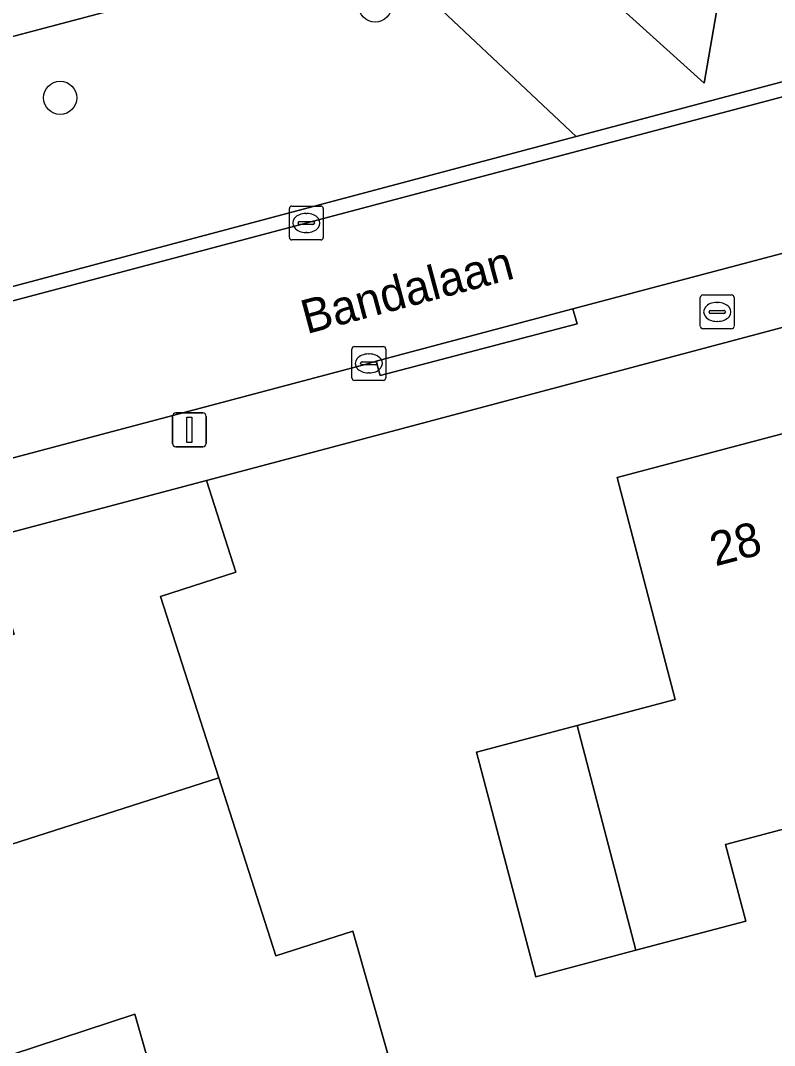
# Model space of a CAD drawing. Extents: x 162879 to 165540, y 384011 to 385181.
# Drawn here: x 163800.4 to 163822.64, y 384414.7 to 384444.93 of the extents above; entities that cross this region are included whole.
import ezdxf

# ---------------------------------------------------------------- set-up
doc = ezdxf.new("R2010")
doc.units = 0
for name, color, linetype in [('IMGEO_Boom', 7, 'Continuous'), ('IMGEO_Brandkraan', 7, 'Continuous'), ('IMGEO_Erf', 7, 'Continuous'), ('IMGEO_Groenvoorziening', 7, 'Continuous'), ('IMGEO_Haag', 7, 'Continuous'), ('IMGEO_Kolk', 7, 'Continuous'), ('IMGEO_Lichtmast', 7, 'Continuous'), ('IMGEO_Muur', 7, 'Continuous'), ('IMGEO_Openbare_ruimte_label', 7, 'Continuous'), ('IMGEO_Pand', 7, 'Continuous'), ('IMGEO_Pand_nummerreeks', 7, 'Continuous'), ('IMGEO_Rijbaan_lokaal_open', 7, 'Continuous'), ('IMGEO_Voetpad_halfverhard', 7, 'Continuous'), ('IMGEO_Voetpad_open', 7, 'Continuous')]:
    doc.layers.add(name, color=color, linetype=linetype)

msp = doc.modelspace()

# ---------------------------------------------------------------- linework, layer by layer
at = {"layer": 'IMGEO_Boom'}
for centre in [(163810.857, 384445.378), (163801.568, 384442.651)]:
    msp.add_circle(centre, 0.489, dxfattribs=at)
at = {"layer": 'IMGEO_Brandkraan'}
for p, q in [((163820.447, 384435.912), (163820.447, 384436.764)), ((163820.522, 384436.838), (163821.374, 384436.838)), ((163821.448, 384436.764), (163821.448, 384435.912)), ((163820.706, 384436.332), (163820.706, 384436.344)), ((163820.749, 384436.381), (163821.147, 384436.381)), ((163820.935, 384436.618), (163820.96, 384436.618)), ((163821.19, 384436.344), (163821.19, 384436.332)), ((163821.144, 384436.295), (163820.746, 384436.295)), ((163820.958, 384436.058), (163820.933, 384436.058)), ((163821.374, 384435.838), (163820.522, 384435.838))]:
    msp.add_line(p, q, dxfattribs=at)
for points in [[(163820.447, 384435.912), (163820.447, 384436.764)], [(163820.522, 384436.838), (163821.374, 384436.838)], [(163821.448, 384436.764), (163821.448, 384435.912)], [(163821.374, 384435.838), (163820.522, 384435.838)]]:
    msp.add_lwpolyline(points, dxfattribs=at)
for centre, radius, start, end in [((163820.524, 384436.762), 0.0765, 91.552, 178.448), ((163820.524, 384436.762), 0.0765, 91.552, 178.448), ((163821.372, 384436.762), 0.0765, 1.552, 88.448), ((163821.372, 384436.762), 0.0765, 1.552, 88.448), ((163820.746, 384436.341), 0.0403, 85.8775, 175.7526), ((163821.151, 384436.343), 0.0386, 1.7309, 96.639), ((163820.743, 384436.331), 0.0366, 178.938, 274.7102), ((163821.147, 384436.338), 0.043, 264.8664, 352.4533), ((163820.524, 384435.914), 0.0765, 181.552, 268.448), ((163820.524, 384435.914), 0.0765, 181.552, 268.448), ((163821.372, 384435.914), 0.0765, 271.552, 358.448), ((163821.372, 384435.914), 0.0765, 271.552, 358.448)]:
    msp.add_arc(centre, radius, start, end, dxfattribs=at)
for centre, major_axis, ratio, start_param, end_param in [((163820.934, 384436.338), (-0.387, 0.002), 0.722429, 4.712389, 7.853982), ((163820.959, 384436.338), (-0.39, 0.002), 0.717154, 1.570796, 4.712389)]:
    msp.add_ellipse(centre, major_axis=major_axis, ratio=ratio, start_param=start_param, end_param=end_param, dxfattribs=at)
at = {"layer": 'IMGEO_Erf'}
for points in [[(163844.085, 384441.522), (163811.331, 384432.813), (163805.887, 384431.366), (163806.752, 384428.658), (163804.524, 384427.941), (163806.243, 384422.592), (163807.931, 384417.34), (163810.195, 384418.068), (163811.223, 384414.483)], [(163826.572, 384422.049), (163821.196, 384420.622), (163821.794, 384418.37), (163818.545, 384417.508), (163815.6, 384416.726), (163813.843, 384423.347), (163816.817, 384424.136), (163819.71, 384424.904), (163817.994, 384431.451), (163823.678, 384432.96)], [(163804.622, 384412.635), (163803.766, 384415.619), (163797.929, 384413.701), (163797.388, 384415.352), (163796.816, 384415.168), (163795.534, 384419.157), (163793.736, 384424.755), (163800.21, 384426.836), (163799.316, 384429.621), (163790.794, 384427.333)]]:
    msp.add_lwpolyline(points, dxfattribs=at)
at = {"layer": 'IMGEO_Groenvoorziening'}
for points in [[(163846.564, 384455.941), (163848.959, 384450.828), (163848.448, 384449.933), (163839.54, 384447.563), (163836.128, 384446.655), (163824.084, 384443.45), (163816.786, 384441.509), (163786.859, 384433.545), (163782.654, 384432.426), (163775.562, 384430.545), (163773.371, 384437.23)], [(163773.081, 384436.833), (163775.3, 384430.061), (163777.69, 384430.711), (163782.356, 384431.947), (163812.597, 384439.959), (163829.593, 384444.462), (163830.022, 384444.577), (163841.66, 384447.709), (163843.285, 384448.142), (163848.713, 384449.59)]]:
    msp.add_lwpolyline(points, dxfattribs=at)
for points in [[(163826.162, 384451.348), (163822.181, 384450.302), (163821.789, 384450.2), (163820.561, 384443.081), (163814.756, 384448.336), (163810.694, 384447.259), (163816.786, 384441.509), (163824.084, 384443.45)], [(163821.789, 384450.2), (163814.756, 384448.336), (163820.561, 384443.081)], [(163816.786, 384441.509), (163810.694, 384447.259), (163790.298, 384441.853), (163786.859, 384433.545)]]:
    msp.add_lwpolyline(points, close=True, dxfattribs=at)
at = {"layer": 'IMGEO_Haag'}
for points in [[(163846.564, 384455.941), (163848.959, 384450.828), (163848.448, 384449.933), (163839.54, 384447.563), (163836.128, 384446.655), (163824.084, 384443.45), (163816.786, 384441.509), (163786.859, 384433.545), (163782.654, 384432.426), (163775.562, 384430.545), (163773.371, 384437.23)], [(163773.081, 384436.833), (163775.3, 384430.061), (163777.69, 384430.711), (163782.356, 384431.947), (163812.597, 384439.959), (163829.593, 384444.462), (163830.022, 384444.577), (163841.66, 384447.709), (163843.285, 384448.142), (163848.713, 384449.59)]]:
    msp.add_lwpolyline(points, dxfattribs=at)
at = {"layer": 'IMGEO_Kolk'}
for p, q in [((163808.327, 384438.535), (163808.327, 384439.387)), ((163808.402, 384439.461), (163809.254, 384439.461)), ((163809.328, 384439.387), (163809.328, 384438.535)), ((163808.815, 384439.241), (163808.84, 384439.241)), ((163808.586, 384438.955), (163808.586, 384438.967)), ((163809.024, 384438.918), (163808.626, 384438.918)), ((163808.629, 384439.004), (163809.027, 384439.004)), ((163809.07, 384438.967), (163809.07, 384438.955)), ((163809.254, 384438.461), (163808.402, 384438.461)), ((163808.838, 384438.681), (163808.813, 384438.681)), ((163810.171, 384434.391), (163810.171, 384435.243)), ((163810.246, 384435.317), (163811.098, 384435.317)), ((163811.172, 384435.243), (163811.172, 384434.391)), ((163810.473, 384434.86), (163810.871, 384434.86)), ((163810.659, 384435.097), (163810.684, 384435.097)), ((163810.43, 384434.811), (163810.43, 384434.823)), ((163810.868, 384434.774), (163810.47, 384434.774)), ((163810.682, 384434.537), (163810.657, 384434.537)), ((163810.914, 384434.823), (163810.914, 384434.811)), ((163811.098, 384434.317), (163810.246, 384434.317))]:
    msp.add_line(p, q, dxfattribs=at)
for points in [[(163808.327, 384438.535), (163808.327, 384439.387)], [(163808.402, 384439.461), (163809.254, 384439.461)], [(163809.328, 384439.387), (163809.328, 384438.535)], [(163809.254, 384438.461), (163808.402, 384438.461)], [(163810.171, 384434.391), (163810.171, 384435.243)], [(163810.246, 384435.317), (163811.098, 384435.317)], [(163811.172, 384435.243), (163811.172, 384434.391)], [(163811.098, 384434.317), (163810.246, 384434.317)]]:
    msp.add_lwpolyline(points, dxfattribs=at)
for centre, radius, start, end in [((163808.404, 384439.385), 0.0765, 91.552, 178.448), ((163808.404, 384439.385), 0.0765, 91.552, 178.448), ((163809.252, 384439.385), 0.0765, 1.552, 88.448), ((163809.252, 384439.385), 0.0765, 1.552, 88.448), ((163808.626, 384438.964), 0.0403, 85.8775, 175.7526), ((163808.623, 384438.954), 0.0366, 178.938, 274.7102), ((163809.027, 384438.961), 0.043, 264.8664, 352.4533), ((163809.031, 384438.966), 0.0386, 1.7309, 96.639), ((163808.404, 384438.537), 0.0765, 181.552, 268.448), ((163808.404, 384438.537), 0.0765, 181.552, 268.448), ((163809.252, 384438.537), 0.0765, 271.552, 358.448), ((163809.252, 384438.537), 0.0765, 271.552, 358.448), ((163810.248, 384435.241), 0.0765, 91.552, 178.448), ((163810.248, 384435.241), 0.0765, 91.552, 178.448), ((163811.096, 384435.241), 0.0765, 1.552, 88.448), ((163811.096, 384435.241), 0.0765, 1.552, 88.448), ((163810.47, 384434.82), 0.0403, 85.8775, 175.7526), ((163810.875, 384434.822), 0.0386, 1.7309, 96.639), ((163810.467, 384434.81), 0.0366, 178.938, 274.7102), ((163810.871, 384434.817), 0.043, 264.8664, 352.4533), ((163810.248, 384434.393), 0.0765, 181.552, 268.448), ((163810.248, 384434.393), 0.0765, 181.552, 268.448), ((163811.096, 384434.393), 0.0765, 271.552, 358.448), ((163811.096, 384434.393), 0.0765, 271.552, 358.448)]:
    msp.add_arc(centre, radius, start, end, dxfattribs=at)
for centre, major_axis, ratio, start_param, end_param in [((163808.814, 384438.961), (-0.387, 0.002), 0.722429, 4.712389, 7.853982), ((163808.839, 384438.961), (-0.39, 0.002), 0.717154, 1.570796, 4.712389), ((163810.658, 384434.817), (-0.387, 0.002), 0.722429, 4.712389, 7.853982), ((163810.683, 384434.817), (-0.39, 0.002), 0.717154, 1.570796, 4.712389)]:
    msp.add_ellipse(centre, major_axis=major_axis, ratio=ratio, start_param=start_param, end_param=end_param, dxfattribs=at)
at = {"layer": 'IMGEO_Lichtmast'}
for p, q in [((163804.982, 384433.357), (163805.772, 384433.357)), ((163805.772, 384433.357), (163804.982, 384433.357)), ((163804.882, 384432.457), (163804.882, 384433.257)), ((163804.882, 384433.257), (163804.882, 384432.457)), ((163805.872, 384433.257), (163805.872, 384432.457)), ((163805.872, 384432.457), (163805.872, 384433.257)), ((163805.772, 384432.357), (163804.982, 384432.357)), ((163804.982, 384432.357), (163805.772, 384432.357))]:
    msp.add_line(p, q, dxfattribs=at)
msp.add_lwpolyline([(163805.302, 384433.232), (163805.452, 384433.232), (163805.452, 384432.482), (163805.302, 384432.482), (163805.302, 384433.232)], dxfattribs=at)
for centre, start, end in [((163804.982, 384433.257), 90, 180), ((163804.982, 384433.257), 90, 180), ((163805.772, 384433.257), 0, 90), ((163805.772, 384433.257), 360, 90), ((163804.982, 384432.457), 180, 270), ((163804.982, 384432.457), 180, 270), ((163805.772, 384432.457), 270, 0), ((163805.772, 384432.457), 270, 0)]:
    msp.add_arc(centre, 0.1, start, end, dxfattribs=at)
at = {"layer": 'IMGEO_Muur'}
msp.add_lwpolyline([(163811.331, 384432.813), (163805.887, 384431.366)], dxfattribs=at)
at = {"layer": 'IMGEO_Pand'}
for points in [[(163826.572, 384422.049), (163823.678, 384432.96), (163817.994, 384431.451), (163819.71, 384424.904), (163816.817, 384424.136), (163818.545, 384417.508), (163821.794, 384418.37), (163821.196, 384420.622)], [(163806.243, 384422.592), (163804.524, 384427.941), (163806.752, 384428.658), (163805.887, 384431.366), (163799.316, 384429.621), (163800.21, 384426.836), (163793.736, 384424.755), (163795.534, 384419.157)], [(163818.545, 384417.508), (163816.817, 384424.136), (163813.843, 384423.347), (163815.6, 384416.726)], [(163806.243, 384422.592), (163795.534, 384419.157), (163796.816, 384415.168), (163797.388, 384415.352), (163797.929, 384413.701), (163803.766, 384415.619), (163804.622, 384412.635), (163811.223, 384414.483), (163810.195, 384418.068), (163807.931, 384417.34)]]:
    msp.add_lwpolyline(points, close=True, dxfattribs=at)
at = {"layer": 'IMGEO_Rijbaan_lokaal_open'}
for points in [[(163816.688, 384436.424), (163827.864, 384439.385), (163828.078, 384439.436), (163833.898, 384440.995), (163844.487, 384443.826), (163843.285, 384448.142), (163841.66, 384447.709), (163830.022, 384444.577), (163829.593, 384444.462), (163812.597, 384439.959), (163782.356, 384431.947), (163785.005, 384423.713)], [(163789.071, 384429.007), (163790.022, 384429.323), (163790.242, 384429.393), (163810.672, 384434.817), (163810.892, 384434.883), (163816.688, 384436.424)]]:
    msp.add_lwpolyline(points, dxfattribs=at)
at = {"layer": 'IMGEO_Voetpad_halfverhard'}
msp.add_lwpolyline([(163773.948, 384437.519), (163786.21, 384440.769), (163790.298, 384441.853), (163810.694, 384447.259), (163814.756, 384448.336), (163821.789, 384450.2), (163822.181, 384450.302), (163826.162, 384451.348), (163831.897, 384452.856), (163835.315, 384453.754), (163844.879, 384455.947), (163846.081, 384455.943), (163849.575, 384457.122), (163849.689, 384457.154), (163850.77, 384457.592), (163850.988, 384457.126), (163851.355, 384457.285), (163854.334, 384458.567), (163859.733, 384460.009), (163885.67, 384466.934)], dxfattribs=at)
at = {"layer": 'IMGEO_Voetpad_open'}
for points in [[(163844.487, 384443.826), (163833.898, 384440.995), (163834.015, 384440.558), (163828.203, 384439.02), (163828.078, 384439.436), (163827.864, 384439.385), (163816.688, 384436.424), (163816.813, 384435.986), (163811.005, 384434.458), (163810.892, 384434.883), (163810.672, 384434.817), (163790.242, 384429.393), (163790.022, 384429.323), (163789.071, 384429.007)], [(163805.887, 384431.366), (163811.331, 384432.813), (163844.085, 384441.522)], [(163790.794, 384427.333), (163799.316, 384429.621), (163805.887, 384431.366)]]:
    msp.add_lwpolyline(points, dxfattribs=at)
msp.add_lwpolyline([(163810.892, 384434.883), (163811.005, 384434.458), (163816.813, 384435.986), (163816.688, 384436.424)], close=True, dxfattribs=at)

# ---------------------------------------------------------------- texts
at = {"layer": 'IMGEO_Openbare_ruimte_label'}
msp.add_text('Bandalaan', height=1, rotation=15.0089, dxfattribs=at).set_placement((163808.835, 384435.679))
at = {"layer": 'IMGEO_Pand_nummerreeks'}
msp.add_text('28', height=1, rotation=14.8705, dxfattribs=at).set_placement((163820.892, 384428.827))

doc.saveas('drawing.dxf')
